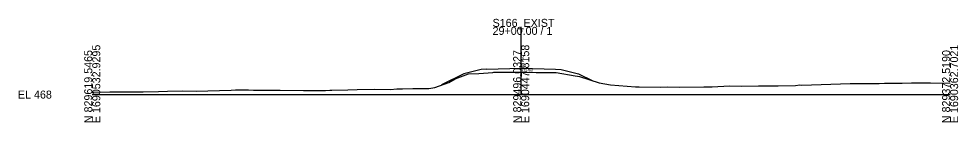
# Model space of a CAD drawing. Extents: x 1621104 to 1621433, y 1192880 to 1199414.
# Drawn here: x 1621104.2 to 1621432.7, y 1194879.5 to 1194915.8 of the extents above; entities that cross this region are included whole.
import ezdxf

# ---------------------------------------------------------------- set-up
doc = ezdxf.new("R2010")
doc.units = 0
for name, color, linetype in [('RD_GPK_XS_Cell', 7, 'Continuous'), ('RD_XS_EarthShd', 7, 'Continuous'), ('RD_XS_ExGround', 7, 'Continuous'), ('RD_XS_Pave', 7, 'Continuous'), ('RD_XS_TieSlope', 7, 'Continuous'), ('RD_XS_TX_Elev_EX', 7, 'Continuous'), ('RD_XS_TX_Elev_PR', 7, 'Continuous')]:
    doc.layers.add(name, color=color, linetype=linetype)

msp = doc.modelspace()

# ---------------------------------------------------------------- linework, layer by layer
at = {"layer": 'RD_GPK_XS_Cell'}
for p, q in [((1621279.86, 1194889.24), (1621279.86, 1194912.97)), ((1621129.86, 1194889.24), (1621279.86, 1194889.24)), ((1621279.86, 1194889.24), (1621429.86, 1194889.24))]:
    msp.add_line(p, q, dxfattribs=at)
at = {"layer": 'RD_XS_EarthShd'}
for p, q in [((1621267.86, 1194898.2), (1621265.86, 1194898.04)), ((1621291.86, 1194898.2), (1621293.86, 1194898.04))]:
    msp.add_line(p, q, dxfattribs=at)
at = {"layer": 'RD_XS_ExGround'}
msp.add_lwpolyline([(1621129.86, 1194890.1), (1621130.42, 1194890.11), (1621135.99, 1194890.17), (1621142.93, 1194890.18), (1621147.7, 1194890.22), (1621153.02, 1194890.28), (1621156.2, 1194890.45), (1621161.34, 1194890.54), (1621166.24, 1194890.45), (1621178.44, 1194890.81), (1621179.92, 1194890.85), (1621184.53, 1194890.87), (1621186.3, 1194890.82), (1621189.32, 1194890.77), (1621195.62, 1194890.78), (1621203.71, 1194890.66), (1621204.16, 1194890.66), (1621211.42, 1194890.72), (1621212.92, 1194890.8), (1621213.66, 1194890.79), (1621219.27, 1194890.87), (1621222.52, 1194890.99), (1621228.63, 1194891.13), (1621234.19, 1194891.07), (1621236.38, 1194891.22), (1621237.2, 1194891.25), (1621238.36, 1194891.27), (1621241.98, 1194891.32), (1621247.57, 1194891.42), (1621249.67, 1194891.77), (1621254.54, 1194893.51), (1621256.75, 1194894.76), (1621261.43, 1194896.48), (1621265.06, 1194896.68), (1621269.97, 1194897.03), (1621270.34, 1194897.04), (1621279.21, 1194897.15), (1621279.86, 1194897.14), (1621281.89, 1194897.12), (1621285.1, 1194896.99), (1621287.23, 1194896.92), (1621291.74, 1194896.94), (1621292.09, 1194896.93), (1621298.7, 1194895.85), (1621299.53, 1194895.74), (1621300.23, 1194895.53), (1621307.13, 1194893.35), (1621311.09, 1194892.63), (1621319.86, 1194892.01), (1621321.18, 1194891.93), (1621328.72, 1194891.86), (1621331.13, 1194891.9), (1621335.28, 1194891.87), (1621343.73, 1194891.93), (1621344.41, 1194891.95), (1621346.64, 1194892), (1621352.76, 1194892.26), (1621356.85, 1194892.23), (1621362.83, 1194892.3), (1621364.12, 1194892.34), (1621369.76, 1194892.27), (1621375.85, 1194892.47), (1621377.34, 1194892.6), (1621378, 1194892.59), (1621394.94, 1194893.08), (1621405, 1194893.09), (1621406.91, 1194893.22), (1621413.05, 1194893.26), (1621416.33, 1194893.36), (1621417.58, 1194893.41), (1621418.43, 1194893.4), (1621423.01, 1194893.33), (1621429.86, 1194893.21)], dxfattribs=at)
at = {"layer": 'RD_XS_Pave'}
for p, q in [((1621267.86, 1194898.2), (1621279.86, 1194898.44)), ((1621279.86, 1194898.44), (1621291.86, 1194898.2))]:
    msp.add_line(p, q, dxfattribs=at)
at = {"layer": 'RD_XS_TieSlope'}
for p, q in [((1621259.86, 1194896.54), (1621251.99, 1194892.6)), ((1621265.86, 1194898.04), (1621259.86, 1194896.54)), ((1621293.86, 1194898.04), (1621299.86, 1194896.54)), ((1621299.86, 1194896.54), (1621304.7, 1194894.12))]:
    msp.add_line(p, q, dxfattribs=at)

# ---------------------------------------------------------------- texts
at = {"layer": 'RD_GPK_XS_Cell'}
for s, p in [('S166_EXIST', (1621269.86, 1194912.97)), ('29+00.00 / 1', (1621269.86, 1194910.17)), ('EL 468', (1621103.86, 1194887.84))]:
    msp.add_text(s, height=2.8, dxfattribs=at).set_placement(p)
for s, p in [('E 1690532.9295', (1621132.66, 1194879.24)), ('E 1690447.8158', (1621282.66, 1194879.24)), ('E 1690362.7021', (1621432.66, 1194879.24)), ('N 829619.5465', (1621129.86, 1194879.24)), ('N 829496.0327', (1621279.86, 1194879.24)), ('N 829372.5190', (1621429.86, 1194879.24))]:
    msp.add_text(s, height=2.8, rotation=90, dxfattribs=at).set_placement(p)
at = {"layer": 'RD_XS_TX_Elev_EX'}
msp.add_text('475.90', height=1, dxfattribs=at).set_placement((1621279.76, 1194897.24))
at = {"layer": 'RD_XS_TX_Elev_PR'}
msp.add_text(' 477.20', height=1, rotation=90, dxfattribs=at).set_placement((1621280.86, 1194898.44))

doc.saveas('drawing.dxf')
